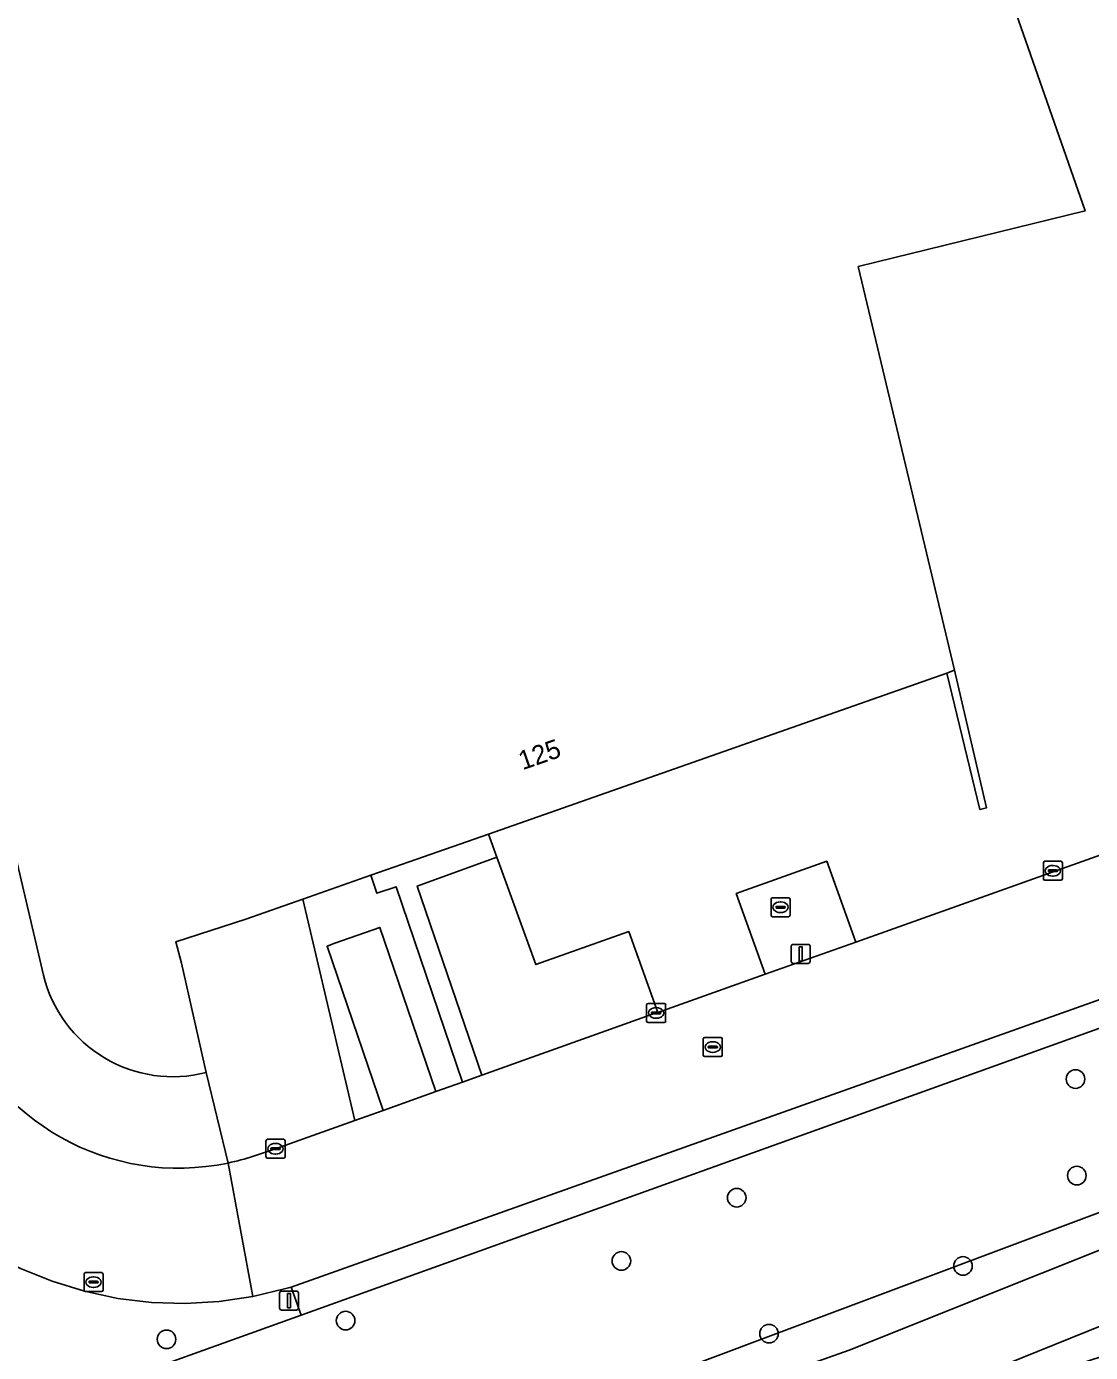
# Model space of a CAD drawing. Extents: x 161385 to 162589, y 388479 to 389756.
# Drawn here: x 162123.9 to 162179.9, y 388516.9 to 388586.7 of the extents above; entities that cross this region are included whole.
import ezdxf

# ---------------------------------------------------------------- set-up
doc = ezdxf.new("R2010")
doc.units = 0
for name, color, linetype in [('IMGEO_Berm_groen', 7, 'Continuous'), ('IMGEO_Boom', 7, 'Continuous'), ('IMGEO_Erf', 7, 'Continuous'), ('IMGEO_Fietspad_gesloten', 7, 'Continuous'), ('IMGEO_Groenvoorziening', 7, 'Continuous'), ('IMGEO_Kolk', 7, 'Continuous'), ('IMGEO_Lichtmast', 7, 'Continuous'), ('IMGEO_Loofbos', 7, 'Continuous'), ('IMGEO_Muur', 7, 'Continuous'), ('IMGEO_Pand', 7, 'Continuous'), ('IMGEO_Pand_nummerreeks', 7, 'Continuous'), ('IMGEO_Rijbaan_lokaal_gesloten', 7, 'Continuous'), ('IMGEO_Rioolput', 7, 'Continuous'), ('IMGEO_Voetpad_open', 7, 'Continuous')]:
    doc.layers.add(name, color=color, linetype=linetype)

msp = doc.modelspace()

# ---------------------------------------------------------------- linework, layer by layer
at = {"layer": 'IMGEO_Berm_groen'}
for points in [[(162319.902, 388581.48), (162316.848, 388580.491), (162315.105, 388579.927), (162225.932, 388551.675), (162217.932, 388548.854), (162137.852, 388520.378), (162138.38, 388518.892), (162215.574, 388546.64), (162252.986, 388559.158)], [(162338.365, 388578.901), (162338.047, 388580.195), (162324.599, 388576.081), (162287.169, 388563.505), (162279.038, 388561.214), (162264.796, 388556.642), (162259.025, 388554.101), (162254.71, 388552.825), (162240.969, 388547.955), (162222.876, 388540.549), (162201.4, 388532.175), (162133.055, 388506.534)], [(162117.736, 388502.546), (162117.232, 388501.49), (162117.576, 388500.015), (162117.372, 388499.941), (162117.395, 388499.82), (162117.419, 388499.693), (162120.579, 388500.721), (162128.073, 388503.157), (162167.231, 388517.05), (162197.575, 388529.185), (162209.962, 388534.05)], [(162205.548, 388528.526), (162201.647, 388526.877), (162165.808, 388512.398), (162164.054, 388511.643), (162164.193, 388511.274), (162170.029, 388513.254), (162177.133, 388515.609), (162180.534, 388516.727), (162189.5, 388519.675), (162197.568, 388522.357), (162205.057, 388524.828), (162209.464, 388526.309), (162209.466, 388526.31)]]:
    msp.add_lwpolyline(points, dxfattribs=at)
at = {"layer": 'IMGEO_Boom'}
for centre in [(162179.146, 388531.324), (162179.214, 388526.243), (162161.31, 388525.078), (162155.237, 388521.751), (162173.222, 388521.486), (162140.718, 388518.61), (162131.291, 388517.624), (162163.009, 388517.923)]:
    msp.add_circle(centre, 0.489, dxfattribs=at)
at = {"layer": 'IMGEO_Erf'}
msp.add_lwpolyline([(162166.514, 388614.639), (162179.646, 388577.025), (162167.708, 388574.1), (162172.773, 388552.843), (162174.465, 388545.605), (162174.113, 388545.508), (162172.374, 388552.698), (162148.243, 388544.225), (162148.686, 388543.003), (162150.733, 388537.349), (162155.629, 388539.084), (162157.155, 388534.834), (162162.809, 388536.844), (162161.281, 388541.085), (162166.052, 388542.788), (162167.575, 388538.539), (162178.209, 388542.32), (162196.492, 388548.826)], dxfattribs=at)
at = {"layer": 'IMGEO_Fietspad_gesloten'}
for points in [[(162209.962, 388534.05), (162197.575, 388529.185), (162167.231, 388517.05), (162128.073, 388503.157), (162120.579, 388500.721), (162117.419, 388499.693), (162117.948, 388496.859), (162117.997, 388496.595), (162118.094, 388496.076), (162118.244, 388495.27), (162120.577, 388496.032), (162127.04, 388498.284), (162134.191, 388500.77), (162137.466, 388501.908)], [(162146.842, 388505.334), (162151.538, 388507.067), (162152.911, 388507.538), (162158.605, 388509.443), (162163.376, 388510.997), (162164.193, 388511.274), (162164.054, 388511.643), (162165.808, 388512.398), (162201.647, 388526.877), (162205.548, 388528.526)]]:
    msp.add_lwpolyline(points, dxfattribs=at)
at = {"layer": 'IMGEO_Groenvoorziening'}
for points in [[(162124.805, 388536.795), (162115.306, 388577.305), (162122.082, 388578.894), (162117.232, 388599.583), (162117.152, 388599.924), (162110.66, 388597.955), (162110.575, 388598.065), (162106.439, 388596.797), (162105.574, 388595.608), (162106.147, 388593.262), (162110.381, 388575.536), (162114.984, 388556.229), (162119.589, 388536.79), (162120.01, 388535.051)], [(162134.528, 388526.905), (162133.381, 388531.67)], [(162124.65, 388513.957), (162138.38, 388518.892), (162137.852, 388520.378), (162137.57, 388520.294), (162135.832, 388519.875), (162134.064, 388519.612), (162132.28, 388519.508), (162130.493, 388519.564), (162128.718, 388519.78), (162126.97, 388520.153), (162125.263, 388520.681), (162123.609, 388521.359)]]:
    msp.add_lwpolyline(points, dxfattribs=at)
for points in [[(162155.629, 388539.084), (162150.733, 388537.349), (162148.686, 388543.003), (162144.492, 388541.484), (162147.884, 388531.527), (162157.068, 388534.803), (162157.155, 388534.834)], [(162167.575, 388538.539), (162166.052, 388542.788), (162161.281, 388541.085), (162162.809, 388536.844)], [(162146.877, 388531.168), (162143.375, 388541.449), (162142.365, 388541.103), (162142.05, 388542.051), (162138.46, 388540.79), (162141.211, 388529.146), (162142.688, 388529.673), (162139.742, 388538.317), (162140.151, 388538.486), (162142.515, 388539.31), (162145.47, 388530.665)]]:
    msp.add_lwpolyline(points, close=True, dxfattribs=at)
for centre, radius, start, end in [((162131.626, 388538.472), 7.024, 193.81055, 284.46455), ((162131.921, 388539.268), 12.635, 199.49753, 281.9092)]:
    msp.add_arc(centre, radius, start, end, dxfattribs=at)
at = {"layer": 'IMGEO_Kolk'}
for p, q in [((162177.453, 388541.862), (162177.453, 388542.714)), ((162177.528, 388542.788), (162178.38, 388542.788)), ((162177.941, 388542.568), (162177.966, 388542.568)), ((162178.454, 388542.714), (162178.454, 388541.862)), ((162177.712, 388542.282), (162177.712, 388542.294)), ((162178.15, 388542.245), (162177.752, 388542.245)), ((162177.755, 388542.331), (162178.153, 388542.331)), ((162177.964, 388542.008), (162177.939, 388542.008)), ((162178.196, 388542.294), (162178.196, 388542.282)), ((162178.38, 388541.788), (162177.528, 388541.788)), ((162156.567, 388534.378), (162156.567, 388535.23)), ((162156.642, 388535.304), (162157.494, 388535.304)), ((162156.869, 388534.847), (162157.267, 388534.847)), ((162157.055, 388535.084), (162157.08, 388535.084)), ((162157.568, 388535.23), (162157.568, 388534.378)), ((162157.494, 388534.304), (162156.642, 388534.304)), ((162156.826, 388534.798), (162156.826, 388534.81)), ((162157.264, 388534.761), (162156.866, 388534.761)), ((162157.078, 388534.524), (162157.053, 388534.524)), ((162157.31, 388534.81), (162157.31, 388534.798)), ((162136.527, 388527.229), (162136.527, 388528.081)), ((162136.602, 388528.155), (162137.454, 388528.155)), ((162137.015, 388527.935), (162137.04, 388527.935)), ((162137.528, 388528.081), (162137.528, 388527.229)), ((162136.786, 388527.649), (162136.786, 388527.661)), ((162137.224, 388527.612), (162136.826, 388527.612)), ((162136.829, 388527.698), (162137.227, 388527.698)), ((162137.038, 388527.375), (162137.013, 388527.375)), ((162137.27, 388527.661), (162137.27, 388527.649)), ((162137.454, 388527.155), (162136.602, 388527.155))]:
    msp.add_line(p, q, dxfattribs=at)
for points in [[(162177.453, 388541.862), (162177.453, 388542.714)], [(162177.528, 388542.788), (162178.38, 388542.788)], [(162178.454, 388542.714), (162178.454, 388541.862)], [(162178.38, 388541.788), (162177.528, 388541.788)], [(162156.567, 388534.378), (162156.567, 388535.23)], [(162156.642, 388535.304), (162157.494, 388535.304)], [(162157.568, 388535.23), (162157.568, 388534.378)], [(162157.494, 388534.304), (162156.642, 388534.304)], [(162136.527, 388527.229), (162136.527, 388528.081)], [(162136.602, 388528.155), (162137.454, 388528.155)], [(162137.528, 388528.081), (162137.528, 388527.229)], [(162137.454, 388527.155), (162136.602, 388527.155)]]:
    msp.add_lwpolyline(points, dxfattribs=at)
for centre, radius, start, end in [((162177.53, 388542.712), 0.0765, 91.55205, 178.44795), ((162177.53, 388542.712), 0.0765, 91.55205, 178.44795), ((162178.378, 388542.712), 0.0765, 1.55205, 88.44795), ((162178.378, 388542.712), 0.0765, 1.55205, 88.44795), ((162177.53, 388541.864), 0.0765, 181.55205, 268.44795), ((162177.53, 388541.864), 0.0765, 181.55205, 268.44795), ((162177.752, 388542.291), 0.0403, 85.87752, 175.75265), ((162177.749, 388542.281), 0.0366, 178.93798, 274.71019), ((162178.153, 388542.288), 0.043, 264.86636, 352.45326), ((162178.157, 388542.293), 0.0386, 1.73085, 96.63898), ((162178.378, 388541.864), 0.0765, 271.55205, 358.44795), ((162178.378, 388541.864), 0.0765, 271.55205, 358.44795), ((162156.644, 388535.228), 0.0765, 91.55205, 178.44795), ((162156.644, 388535.228), 0.0765, 91.55205, 178.44795), ((162156.866, 388534.807), 0.0403, 85.87752, 175.75265), ((162157.271, 388534.809), 0.0386, 1.73085, 96.63898), ((162157.492, 388535.228), 0.0765, 1.55205, 88.44795), ((162157.492, 388535.228), 0.0765, 1.55205, 88.44795), ((162156.644, 388534.38), 0.0765, 181.55205, 268.44795), ((162156.644, 388534.38), 0.0765, 181.55205, 268.44795), ((162156.863, 388534.797), 0.0366, 178.93798, 274.71019), ((162157.267, 388534.804), 0.043, 264.86636, 352.45326), ((162157.492, 388534.38), 0.0765, 271.55205, 358.44795), ((162157.492, 388534.38), 0.0765, 271.55205, 358.44795), ((162136.604, 388528.079), 0.0765, 91.55205, 178.44795), ((162136.604, 388528.079), 0.0765, 91.55205, 178.44795), ((162137.452, 388528.079), 0.0765, 1.55205, 88.44795), ((162137.452, 388528.079), 0.0765, 1.55205, 88.44795), ((162136.604, 388527.231), 0.0765, 181.55205, 268.44795), ((162136.604, 388527.231), 0.0765, 181.55205, 268.44795), ((162136.826, 388527.658), 0.0403, 85.87752, 175.75265), ((162136.823, 388527.648), 0.0366, 178.93798, 274.71019), ((162137.227, 388527.655), 0.043, 264.86636, 352.45326), ((162137.231, 388527.66), 0.0386, 1.73085, 96.63898), ((162137.452, 388527.231), 0.0765, 271.55205, 358.44795), ((162137.452, 388527.231), 0.0765, 271.55205, 358.44795)]:
    msp.add_arc(centre, radius, start, end, dxfattribs=at)
for centre, major_axis, ratio, start_param, end_param in [((162177.94, 388542.288), (-0.387, 0.002), 0.722429, 4.712389, 7.853982), ((162177.965, 388542.288), (-0.39, 0.002), 0.717154, 1.570796, 4.712389), ((162157.054, 388534.804), (-0.387, 0.002), 0.722429, 4.712389, 7.853982), ((162157.079, 388534.804), (-0.39, 0.002), 0.717154, 1.570796, 4.712389), ((162137.014, 388527.655), (-0.387, 0.002), 0.722429, 4.712389, 7.853982), ((162137.039, 388527.655), (-0.39, 0.002), 0.717154, 1.570796, 4.712389)]:
    msp.add_ellipse(centre, major_axis=major_axis, ratio=ratio, start_param=start_param, end_param=end_param, dxfattribs=at)
at = {"layer": 'IMGEO_Lichtmast'}
for p, q in [((162164.278, 388538.412), (162165.068, 388538.412)), ((162165.068, 388538.412), (162164.278, 388538.412)), ((162164.178, 388537.512), (162164.178, 388538.312)), ((162164.178, 388538.312), (162164.178, 388537.512)), ((162165.168, 388538.312), (162165.168, 388537.512)), ((162165.168, 388537.512), (162165.168, 388538.312)), ((162165.068, 388537.412), (162164.278, 388537.412)), ((162164.278, 388537.412), (162165.068, 388537.412)), ((162137.241, 388519.262), (162137.241, 388520.062)), ((162137.241, 388520.062), (162137.241, 388519.262)), ((162137.341, 388520.162), (162138.131, 388520.162)), ((162138.131, 388520.162), (162137.341, 388520.162)), ((162138.231, 388520.062), (162138.231, 388519.262)), ((162138.231, 388519.262), (162138.231, 388520.062)), ((162138.131, 388519.162), (162137.341, 388519.162)), ((162137.341, 388519.162), (162138.131, 388519.162))]:
    msp.add_line(p, q, dxfattribs=at)
for points in [[(162164.598, 388538.287), (162164.748, 388538.287), (162164.748, 388537.537), (162164.598, 388537.537), (162164.598, 388538.287)], [(162137.661, 388520.037), (162137.811, 388520.037), (162137.811, 388519.287), (162137.661, 388519.287), (162137.661, 388520.037)]]:
    msp.add_lwpolyline(points, dxfattribs=at)
for centre, start, end in [((162164.278, 388538.312), 90, 180), ((162164.278, 388538.312), 90, 180), ((162165.068, 388538.312), 0, 90), ((162165.068, 388538.312), 360, 90), ((162164.278, 388537.512), 180, 270), ((162164.278, 388537.512), 180, 270), ((162165.068, 388537.512), 270, 0), ((162165.068, 388537.512), 270, 0), ((162137.341, 388520.062), 90, 180), ((162137.341, 388520.062), 90, 180), ((162138.131, 388520.062), 0, 90), ((162138.131, 388520.062), 360, 90), ((162137.341, 388519.262), 180, 270), ((162137.341, 388519.262), 180, 270), ((162138.131, 388519.262), 270, 0), ((162138.131, 388519.262), 270, 0)]:
    msp.add_arc(centre, 0.1, start, end, dxfattribs=at)
at = {"layer": 'IMGEO_Loofbos'}
for points in [[(162336.532, 388584.978), (162317.268, 388578.974), (162288.362, 388570.488), (162252.986, 388559.158), (162215.574, 388546.64), (162138.38, 388518.892), (162124.65, 388513.957), (162116.698, 388511.605), (162115.545, 388511.3), (162114.423, 388510.894), (162113.342, 388510.388), (162112.311, 388509.789), (162111.337, 388509.099), (162110.429, 388508.325), (162110.008, 388507.915), (162109.734, 388507.207), (162110.01, 388506.497), (162110.485, 388506.096), (162117.232, 388501.49), (162117.736, 388502.546)], [(162133.055, 388506.534), (162201.4, 388532.175), (162222.876, 388540.549), (162240.969, 388547.955), (162254.71, 388552.825), (162259.025, 388554.101), (162264.796, 388556.642), (162279.038, 388561.214), (162287.169, 388563.505), (162324.599, 388576.081), (162338.047, 388580.195)]]:
    msp.add_lwpolyline(points, dxfattribs=at)
at = {"layer": 'IMGEO_Muur'}
msp.add_lwpolyline([(162174.113, 388545.508), (162174.465, 388545.605), (162172.773, 388552.843), (162172.374, 388552.698)], close=True, dxfattribs=at)
at = {"layer": 'IMGEO_Pand'}
msp.add_lwpolyline([(162133.381, 388531.67), (162132.074, 388537.422), (162131.778, 388538.547), (162135.47, 388539.74), (162138.46, 388540.79), (162142.05, 388542.051), (162144.059, 388542.756), (162148.243, 388544.225), (162172.374, 388552.698), (162172.773, 388552.843), (162167.708, 388574.1), (162179.646, 388577.025), (162166.514, 388614.639), (162117.232, 388599.583), (162122.082, 388578.894), (162115.306, 388577.305), (162124.805, 388536.795)], dxfattribs=at)
msp.add_arc((162131.626, 388538.472), 7.024, 193.81055, 284.46455, dxfattribs=at)
at = {"layer": 'IMGEO_Rijbaan_lokaal_gesloten'}
for points in [[(162081.745, 388653.938), (162098.001, 388596.208), (162098.978, 388592.317), (162113.114, 388532.985), (162113.771, 388531.323), (162114.574, 388529.726), (162115.517, 388528.207), (162116.591, 388526.778), (162117.789, 388525.452), (162119.101, 388524.237), (162120.515, 388523.144), (162122.022, 388522.183), (162123.609, 388521.359), (162125.263, 388520.681), (162126.97, 388520.153), (162128.718, 388519.78), (162130.493, 388519.564), (162132.28, 388519.508), (162134.064, 388519.612), (162135.832, 388519.875), (162134.528, 388526.905)], [(162134.528, 388526.905), (162135.832, 388519.875), (162137.57, 388520.294), (162137.852, 388520.378), (162217.932, 388548.854), (162225.932, 388551.675), (162315.105, 388579.927)], [(162196.492, 388548.826), (162178.209, 388542.32), (162167.575, 388538.539), (162162.809, 388536.844), (162157.155, 388534.834), (162157.068, 388534.803), (162147.884, 388531.527), (162146.877, 388531.168), (162145.47, 388530.665), (162142.688, 388529.673), (162141.211, 388529.146), (162137.028, 388527.654), (162135.877, 388527.269)]]:
    msp.add_lwpolyline(points, dxfattribs=at)
for centre, radius, start, end in [((162131.921, 388539.268), 12.635, 199.49753, 281.9092), ((162131.778, 388539.779), 13.164, 282.0584, 288.14254)]:
    msp.add_arc(centre, radius, start, end, dxfattribs=at)
at = {"layer": 'IMGEO_Rioolput'}
for p, q in [((162163.115, 388539.945), (162163.115, 388540.797)), ((162163.19, 388540.871), (162164.042, 388540.871)), ((162163.603, 388540.651), (162163.628, 388540.651)), ((162164.116, 388540.797), (162164.116, 388539.945)), ((162164.042, 388539.871), (162163.19, 388539.871)), ((162163.374, 388540.365), (162163.374, 388540.377)), ((162163.812, 388540.328), (162163.414, 388540.328)), ((162163.417, 388540.414), (162163.815, 388540.414)), ((162163.626, 388540.091), (162163.601, 388540.091)), ((162163.858, 388540.377), (162163.858, 388540.365)), ((162159.622, 388533.51), (162160.474, 388533.51)), ((162159.547, 388532.584), (162159.547, 388533.436)), ((162159.806, 388533.004), (162159.806, 388533.016)), ((162160.244, 388532.967), (162159.846, 388532.967)), ((162159.849, 388533.053), (162160.247, 388533.053)), ((162160.035, 388533.29), (162160.06, 388533.29)), ((162160.29, 388533.016), (162160.29, 388533.004)), ((162160.548, 388533.436), (162160.548, 388532.584)), ((162160.474, 388532.51), (162159.622, 388532.51)), ((162160.058, 388532.73), (162160.033, 388532.73)), ((162126.947, 388520.208), (162126.947, 388521.06)), ((162127.022, 388521.134), (162127.874, 388521.134)), ((162127.435, 388520.914), (162127.46, 388520.914)), ((162127.948, 388521.06), (162127.948, 388520.208)), ((162127.206, 388520.628), (162127.206, 388520.64)), ((162127.644, 388520.591), (162127.246, 388520.591)), ((162127.249, 388520.677), (162127.647, 388520.677)), ((162127.458, 388520.354), (162127.433, 388520.354)), ((162127.69, 388520.64), (162127.69, 388520.628)), ((162127.874, 388520.134), (162127.022, 388520.134))]:
    msp.add_line(p, q, dxfattribs=at)
for points in [[(162163.115, 388539.945), (162163.115, 388540.797)], [(162163.19, 388540.871), (162164.042, 388540.871)], [(162164.116, 388540.797), (162164.116, 388539.945)], [(162164.042, 388539.871), (162163.19, 388539.871)], [(162159.622, 388533.51), (162160.474, 388533.51)], [(162159.547, 388532.584), (162159.547, 388533.436)], [(162160.548, 388533.436), (162160.548, 388532.584)], [(162160.474, 388532.51), (162159.622, 388532.51)], [(162126.947, 388520.208), (162126.947, 388521.06)], [(162127.022, 388521.134), (162127.874, 388521.134)], [(162127.948, 388521.06), (162127.948, 388520.208)], [(162127.874, 388520.134), (162127.022, 388520.134)]]:
    msp.add_lwpolyline(points, dxfattribs=at)
for centre, radius, start, end in [((162163.192, 388540.795), 0.0765, 91.55205, 178.44795), ((162163.192, 388540.795), 0.0765, 91.55205, 178.44795), ((162164.04, 388540.795), 0.0765, 1.55205, 88.44795), ((162164.04, 388540.795), 0.0765, 1.55205, 88.44795), ((162163.192, 388539.947), 0.0765, 181.55205, 268.44795), ((162163.192, 388539.947), 0.0765, 181.55205, 268.44795), ((162163.414, 388540.374), 0.0403, 85.87752, 175.75265), ((162163.411, 388540.364), 0.0366, 178.93798, 274.71019), ((162163.815, 388540.371), 0.043, 264.86636, 352.45326), ((162163.819, 388540.376), 0.0386, 1.73085, 96.63898), ((162164.04, 388539.947), 0.0765, 271.55205, 358.44795), ((162164.04, 388539.947), 0.0765, 271.55205, 358.44795), ((162159.624, 388533.434), 0.0765, 91.55205, 178.44795), ((162159.624, 388533.434), 0.0765, 91.55205, 178.44795), ((162160.472, 388533.434), 0.0765, 1.55205, 88.44795), ((162160.472, 388533.434), 0.0765, 1.55205, 88.44795), ((162159.846, 388533.013), 0.0403, 85.87752, 175.75265), ((162159.843, 388533.003), 0.0366, 178.93798, 274.71019), ((162160.247, 388533.01), 0.043, 264.86636, 352.45326), ((162160.251, 388533.015), 0.0386, 1.73085, 96.63898), ((162159.624, 388532.586), 0.0765, 181.55205, 268.44795), ((162159.624, 388532.586), 0.0765, 181.55205, 268.44795), ((162160.472, 388532.586), 0.0765, 271.55205, 358.44795), ((162160.472, 388532.586), 0.0765, 271.55205, 358.44795), ((162127.024, 388521.058), 0.0765, 91.55205, 178.44795), ((162127.024, 388521.058), 0.0765, 91.55205, 178.44795), ((162127.872, 388521.058), 0.0765, 1.55205, 88.44795), ((162127.872, 388521.058), 0.0765, 1.55205, 88.44795), ((162127.024, 388520.21), 0.0765, 181.55205, 268.44795), ((162127.024, 388520.21), 0.0765, 181.55205, 268.44795), ((162127.246, 388520.637), 0.0403, 85.87752, 175.75265), ((162127.243, 388520.627), 0.0366, 178.93798, 274.71019), ((162127.647, 388520.634), 0.043, 264.86636, 352.45326), ((162127.651, 388520.639), 0.0386, 1.73085, 96.63898), ((162127.872, 388520.21), 0.0765, 271.55205, 358.44795), ((162127.872, 388520.21), 0.0765, 271.55205, 358.44795)]:
    msp.add_arc(centre, radius, start, end, dxfattribs=at)
for centre, major_axis, ratio, start_param, end_param in [((162163.602, 388540.371), (-0.387, 0.002), 0.722429, 4.712389, 7.853982), ((162163.627, 388540.371), (-0.39, 0.002), 0.717154, 1.570796, 4.712389), ((162160.034, 388533.01), (-0.387, 0.002), 0.722429, 4.712389, 7.853982), ((162160.059, 388533.01), (-0.39, 0.002), 0.717154, 1.570796, 4.712389), ((162127.434, 388520.634), (-0.387, 0.002), 0.722429, 4.712389, 7.853982), ((162127.459, 388520.634), (-0.39, 0.002), 0.717154, 1.570796, 4.712389)]:
    msp.add_ellipse(centre, major_axis=major_axis, ratio=ratio, start_param=start_param, end_param=end_param, dxfattribs=at)
at = {"layer": 'IMGEO_Voetpad_open'}
for points in [[(162144.492, 388541.484), (162148.686, 388543.003), (162148.243, 388544.225), (162144.059, 388542.756), (162142.05, 388542.051), (162142.365, 388541.103), (162143.375, 388541.449), (162146.877, 388531.168), (162147.884, 388531.527)], [(162142.515, 388539.31), (162140.151, 388538.486), (162139.742, 388538.317), (162142.688, 388529.673), (162145.47, 388530.665)]]:
    msp.add_lwpolyline(points, close=True, dxfattribs=at)
msp.add_lwpolyline([(162135.877, 388527.269), (162137.028, 388527.654), (162141.211, 388529.146), (162138.46, 388540.79), (162135.47, 388539.74), (162131.778, 388538.547), (162132.074, 388537.422), (162133.381, 388531.67), (162134.528, 388526.905)], dxfattribs=at)
msp.add_arc((162131.778, 388539.779), 13.164, 282.0584, 288.14254, dxfattribs=at)

# ---------------------------------------------------------------- texts
at = {"layer": 'IMGEO_Pand_nummerreeks'}
msp.add_text('125', height=1, rotation=19.21691, dxfattribs=at).set_placement((162150.034, 388547.579))

doc.saveas('drawing.dxf')
